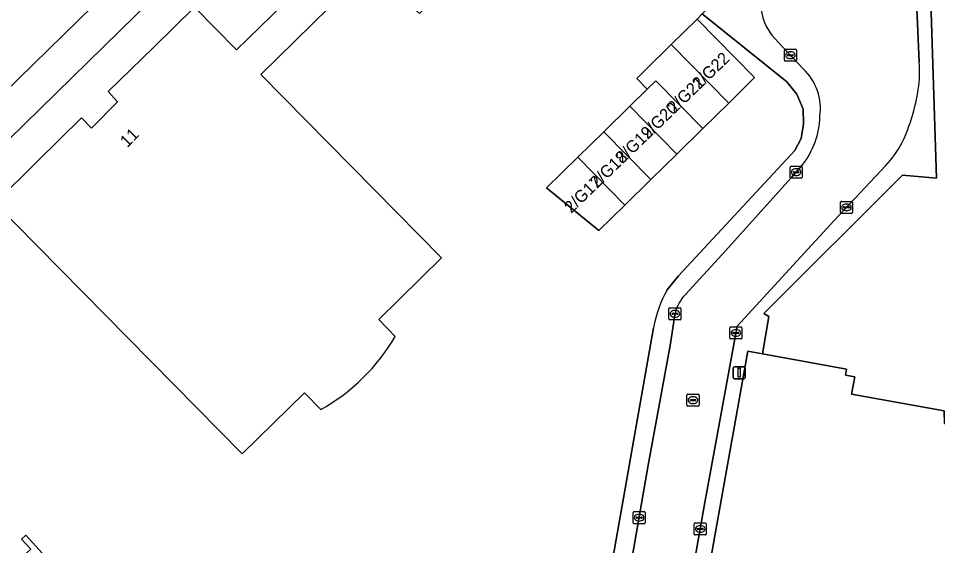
# Model space of a CAD drawing. Extents: x 161402 to 161933, y 381647 to 382315.
# Drawn here: x 161787.9 to 161864.2, y 382075.9 to 382119.7 of the extents above; entities that cross this region are included whole.
import ezdxf

# ---------------------------------------------------------------- set-up
doc = ezdxf.new("R2010")
doc.units = 0
for name, color, linetype in [('IMGEO_Erf', 7, 'Continuous'), ('IMGEO_Kolk', 7, 'Continuous'), ('IMGEO_Lichtmast', 7, 'Continuous'), ('IMGEO_Muur', 7, 'Continuous'), ('IMGEO_Pand', 7, 'Continuous'), ('IMGEO_Pand_nummerreeks', 7, 'Continuous'), ('IMGEO_Rijbaan_lokaal_gesloten', 7, 'Continuous'), ('IMGEO_Rijbaan_lokaal_open', 7, 'Continuous'), ('IMGEO_Rioolput', 7, 'Continuous'), ('IMGEO_Voetpad_gesloten', 7, 'Continuous'), ('IMGEO_Voetpad_open', 7, 'Continuous')]:
    doc.layers.add(name, color=color, linetype=linetype)

msp = doc.modelspace()

# ---------------------------------------------------------------- linework, layer by layer
at = {"layer": 'IMGEO_Erf'}
for points in [[(161864.813, 382185.757), (161863.347, 382184.324), (161863.181, 382184.507), (161862.906, 382184.222), (161863.062, 382184.049), (161858.604, 382179.691), (161858.378, 382179.885), (161858.103, 382179.58), (161858.236, 382179.449), (161857.746, 382179.014), (161845.138, 382166.658), (161826.48, 382148.395), (161804.249, 382126.529), (161781.67, 382104.382)], [(161812.975, 382087.217), (161811.601, 382088.614), (161806.434, 382083.531), (161789.417, 382100.81), (161785.909, 382104.373), (161789.402, 382107.818), (161793.08, 382111.447), (161793.922, 382110.604), (161796.076, 382112.783), (161795.307, 382113.643), (161799.066, 382117.315), (161802.484, 382120.653), (161805.97, 382117.113), (161810.796, 382121.845), (161807.594, 382125.104), (161806.847, 382124.385), (161806.553, 382124.686), (161817.329, 382135.274), (161851.932, 382169.271)], [(161841.719, 382097.173), (161842.653, 382098.334), (161852.306, 382108.752), (161852.848, 382109.73), (161853.024, 382110.948), (161853.013, 382112.179), (161852.482, 382113.414), (161851.638, 382114.461), (161844.618, 382120.095), (161853.957, 382129.629), (161859.667, 382135.458), (161869.551, 382145.549)], [(161826.819, 382125.706), (161821.145, 382120.119), (161820.85, 382120.418), (161821.62, 382121.174), (161817.967, 382124.889), (161807.983, 382115.074), (161822.985, 382099.813), (161817.767, 382094.694), (161819.142, 382093.297)], [(161836.652, 382071.701), (161840.585, 382094.002)], [(161783.505, 382056.018), (161783.263, 382058.701), (161776.645, 382071.618), (161786.037, 382076.43), (161787.222, 382074.116), (161788.878, 382075.604), (161788.117, 382076.444), (161788.484, 382076.777), (161796.387, 382068.043), (161796.339, 382068), (161797.532, 382065.679), (161799.064, 382066.435), (161805.902, 382053.086)]]:
    msp.add_lwpolyline(points, dxfattribs=at)
for points in [[(161885.051, 382130.105), (161872.557, 382142.66), (161863.229, 382133.182), (161864.069, 382106.453), (161861.265, 382106.705), (161849.74, 382095.198), (161850.155, 382094.961), (161849.637, 382091.837), (161856.605, 382090.577), (161856.514, 382090.075), (161857.282, 382089.936), (161857.022, 382088.5), (161864.705, 382087.108), (161864.747, 382086.071), (161881.604, 382083.709), (161886.502, 382086.978)], [(161831.708, 382105.633), (161834.296, 382108.178), (161836.452, 382110.297), (161838.608, 382112.417), (161840.063, 382113.848), (161839.185, 382114.74), (161839.886, 382115.429), (161842.042, 382117.548), (161844.198, 382119.667), (161848.979, 382114.803), (161846.823, 382112.684), (161844.667, 382110.565), (161842.512, 382108.446), (161840.356, 382106.326), (161838.2, 382104.207), (161836.044, 382102.088)]]:
    msp.add_lwpolyline(points, close=True, dxfattribs=at)
for centre, radius, start, end in [((161850.329, 382092.306), 9.89, 150.51987, 170.12441), ((161804.804, 382101.672), 16.604, 299.47668, 329.7093)]:
    msp.add_arc(centre, radius, start, end, dxfattribs=at)
at = {"layer": 'IMGEO_Kolk'}
for p, q in [((161851.446, 382116.238), (161851.446, 382117.09)), ((161851.521, 382117.164), (161852.373, 382117.164)), ((161851.934, 382116.944), (161851.959, 382116.944)), ((161852.447, 382117.09), (161852.447, 382116.238)), ((161852.373, 382116.164), (161851.521, 382116.164)), ((161851.705, 382116.658), (161851.705, 382116.67)), ((161852.143, 382116.621), (161851.745, 382116.621)), ((161851.748, 382116.707), (161852.146, 382116.707)), ((161851.957, 382116.384), (161851.932, 382116.384)), ((161852.189, 382116.67), (161852.189, 382116.658)), ((161851.921, 382106.512), (161851.921, 382107.364)), ((161851.996, 382107.438), (161852.848, 382107.438)), ((161852.18, 382106.932), (161852.18, 382106.944)), ((161852.223, 382106.981), (161852.621, 382106.981)), ((161852.409, 382107.218), (161852.434, 382107.218)), ((161852.664, 382106.944), (161852.664, 382106.932)), ((161852.922, 382107.364), (161852.922, 382106.512)), ((161852.848, 382106.438), (161851.996, 382106.438)), ((161852.618, 382106.895), (161852.22, 382106.895)), ((161852.432, 382106.658), (161852.407, 382106.658)), ((161856.101, 382103.59), (161856.101, 382104.442)), ((161856.176, 382104.516), (161857.028, 382104.516)), ((161856.36, 382104.01), (161856.36, 382104.022)), ((161856.798, 382103.973), (161856.4, 382103.973)), ((161856.403, 382104.059), (161856.801, 382104.059)), ((161856.589, 382104.296), (161856.614, 382104.296)), ((161856.844, 382104.022), (161856.844, 382104.01)), ((161857.102, 382104.442), (161857.102, 382103.59)), ((161857.028, 382103.516), (161856.176, 382103.516)), ((161856.612, 382103.736), (161856.587, 382103.736)), ((161841.861, 382094.749), (161841.861, 382095.601)), ((161841.936, 382095.675), (161842.788, 382095.675)), ((161842.862, 382095.601), (161842.862, 382094.749)), ((161842.12, 382095.169), (161842.12, 382095.181)), ((161842.558, 382095.132), (161842.16, 382095.132)), ((161842.163, 382095.218), (161842.561, 382095.218)), ((161842.372, 382094.895), (161842.347, 382094.895)), ((161842.349, 382095.455), (161842.374, 382095.455)), ((161842.604, 382095.181), (161842.604, 382095.169)), ((161842.788, 382094.675), (161841.936, 382094.675)), ((161846.92, 382093.157), (161846.92, 382094.009)), ((161846.995, 382094.083), (161847.847, 382094.083)), ((161847.921, 382094.009), (161847.921, 382093.157)), ((161847.179, 382093.577), (161847.179, 382093.589)), ((161847.617, 382093.54), (161847.219, 382093.54)), ((161847.222, 382093.626), (161847.62, 382093.626)), ((161847.431, 382093.303), (161847.406, 382093.303)), ((161847.408, 382093.863), (161847.433, 382093.863)), ((161847.663, 382093.589), (161847.663, 382093.577)), ((161847.847, 382093.083), (161846.995, 382093.083)), ((161838.964, 382078.733), (161839.816, 382078.733)), ((161838.889, 382077.807), (161838.889, 382078.659)), ((161839.148, 382078.227), (161839.148, 382078.239)), ((161839.586, 382078.19), (161839.188, 382078.19)), ((161839.191, 382078.276), (161839.589, 382078.276)), ((161839.4, 382077.953), (161839.375, 382077.953)), ((161839.377, 382078.513), (161839.402, 382078.513)), ((161839.632, 382078.239), (161839.632, 382078.227)), ((161839.89, 382078.659), (161839.89, 382077.807)), ((161839.816, 382077.733), (161838.964, 382077.733)), ((161843.958, 382076.869), (161843.958, 382077.721)), ((161844.033, 382077.795), (161844.885, 382077.795)), ((161844.217, 382077.289), (161844.217, 382077.301)), ((161844.655, 382077.252), (161844.257, 382077.252)), ((161844.26, 382077.338), (161844.658, 382077.338)), ((161844.446, 382077.575), (161844.471, 382077.575)), ((161844.701, 382077.301), (161844.701, 382077.289)), ((161844.959, 382077.721), (161844.959, 382076.869)), ((161844.885, 382076.795), (161844.033, 382076.795)), ((161844.469, 382077.015), (161844.444, 382077.015))]:
    msp.add_line(p, q, dxfattribs=at)
for points in [[(161851.446, 382116.238), (161851.446, 382117.09)], [(161851.521, 382117.164), (161852.373, 382117.164)], [(161852.447, 382117.09), (161852.447, 382116.238)], [(161852.373, 382116.164), (161851.521, 382116.164)], [(161851.921, 382106.512), (161851.921, 382107.364)], [(161851.996, 382107.438), (161852.848, 382107.438)], [(161852.922, 382107.364), (161852.922, 382106.512)], [(161852.848, 382106.438), (161851.996, 382106.438)], [(161856.101, 382103.59), (161856.101, 382104.442)], [(161856.176, 382104.516), (161857.028, 382104.516)], [(161857.102, 382104.442), (161857.102, 382103.59)], [(161857.028, 382103.516), (161856.176, 382103.516)], [(161841.861, 382094.749), (161841.861, 382095.601)], [(161841.936, 382095.675), (161842.788, 382095.675)], [(161842.862, 382095.601), (161842.862, 382094.749)], [(161842.788, 382094.675), (161841.936, 382094.675)], [(161846.92, 382093.157), (161846.92, 382094.009)], [(161846.995, 382094.083), (161847.847, 382094.083)], [(161847.921, 382094.009), (161847.921, 382093.157)], [(161847.847, 382093.083), (161846.995, 382093.083)], [(161838.964, 382078.733), (161839.816, 382078.733)], [(161838.889, 382077.807), (161838.889, 382078.659)], [(161839.89, 382078.659), (161839.89, 382077.807)], [(161839.816, 382077.733), (161838.964, 382077.733)], [(161843.958, 382076.869), (161843.958, 382077.721)], [(161844.033, 382077.795), (161844.885, 382077.795)], [(161844.959, 382077.721), (161844.959, 382076.869)], [(161844.885, 382076.795), (161844.033, 382076.795)]]:
    msp.add_lwpolyline(points, dxfattribs=at)
for centre, radius, start, end in [((161851.523, 382117.088), 0.0765, 91.55205, 178.44795), ((161851.523, 382117.088), 0.0765, 91.55205, 178.44795), ((161852.371, 382117.088), 0.0765, 1.55205, 88.44795), ((161852.371, 382117.088), 0.0765, 1.55205, 88.44795), ((161851.523, 382116.24), 0.0765, 181.55205, 268.44795), ((161851.523, 382116.24), 0.0765, 181.55205, 268.44795), ((161851.745, 382116.667), 0.0403, 85.87752, 175.75265), ((161851.742, 382116.657), 0.0366, 178.93798, 274.71019), ((161852.146, 382116.664), 0.043, 264.86636, 352.45326), ((161852.15, 382116.669), 0.0386, 1.73085, 96.63898), ((161852.371, 382116.24), 0.0765, 271.55205, 358.44795), ((161852.371, 382116.24), 0.0765, 271.55205, 358.44795), ((161851.998, 382107.362), 0.0765, 91.55205, 178.44795), ((161851.998, 382107.362), 0.0765, 91.55205, 178.44795), ((161852.22, 382106.941), 0.0403, 85.87752, 175.75265), ((161852.217, 382106.931), 0.0366, 178.93798, 274.71019), ((161852.621, 382106.938), 0.043, 264.86636, 352.45326), ((161852.625, 382106.943), 0.0386, 1.73085, 96.63898), ((161852.846, 382107.362), 0.0765, 1.55205, 88.44795), ((161852.846, 382107.362), 0.0765, 1.55205, 88.44795), ((161851.998, 382106.514), 0.0765, 181.55205, 268.44795), ((161851.998, 382106.514), 0.0765, 181.55205, 268.44795), ((161852.846, 382106.514), 0.0765, 271.55205, 358.44795), ((161852.846, 382106.514), 0.0765, 271.55205, 358.44795), ((161856.178, 382104.44), 0.0765, 91.55205, 178.44795), ((161856.178, 382104.44), 0.0765, 91.55205, 178.44795), ((161856.4, 382104.019), 0.0403, 85.87752, 175.75265), ((161856.397, 382104.009), 0.0366, 178.93798, 274.71019), ((161856.801, 382104.016), 0.043, 264.86636, 352.45326), ((161856.805, 382104.021), 0.0386, 1.73085, 96.63898), ((161857.026, 382104.44), 0.0765, 1.55205, 88.44795), ((161857.026, 382104.44), 0.0765, 1.55205, 88.44795), ((161856.178, 382103.592), 0.0765, 181.55205, 268.44795), ((161856.178, 382103.592), 0.0765, 181.55205, 268.44795), ((161857.026, 382103.592), 0.0765, 271.55205, 358.44795), ((161857.026, 382103.592), 0.0765, 271.55205, 358.44795), ((161841.938, 382095.599), 0.0765, 91.55205, 178.44795), ((161841.938, 382095.599), 0.0765, 91.55205, 178.44795), ((161842.786, 382095.599), 0.0765, 1.55205, 88.44795), ((161842.786, 382095.599), 0.0765, 1.55205, 88.44795), ((161841.938, 382094.751), 0.0765, 181.55205, 268.44795), ((161841.938, 382094.751), 0.0765, 181.55205, 268.44795), ((161842.16, 382095.178), 0.0403, 85.87752, 175.75265), ((161842.157, 382095.168), 0.0366, 178.93798, 274.71019), ((161842.561, 382095.175), 0.043, 264.86636, 352.45326), ((161842.565, 382095.18), 0.0386, 1.73085, 96.63898), ((161842.786, 382094.751), 0.0765, 271.55205, 358.44795), ((161842.786, 382094.751), 0.0765, 271.55205, 358.44795), ((161846.997, 382094.007), 0.0765, 91.55205, 178.44795), ((161846.997, 382094.007), 0.0765, 91.55205, 178.44795), ((161847.845, 382094.007), 0.0765, 1.55205, 88.44795), ((161847.845, 382094.007), 0.0765, 1.55205, 88.44795), ((161847.219, 382093.586), 0.0403, 85.87752, 175.75265), ((161847.216, 382093.576), 0.0366, 178.93798, 274.71019), ((161847.62, 382093.583), 0.043, 264.86636, 352.45326), ((161847.624, 382093.588), 0.0386, 1.73085, 96.63898), ((161846.997, 382093.159), 0.0765, 181.55205, 268.44795), ((161846.997, 382093.159), 0.0765, 181.55205, 268.44795), ((161847.845, 382093.159), 0.0765, 271.55205, 358.44795), ((161847.845, 382093.159), 0.0765, 271.55205, 358.44795), ((161838.966, 382078.657), 0.0765, 91.55205, 178.44795), ((161838.966, 382078.657), 0.0765, 91.55205, 178.44795), ((161839.814, 382078.657), 0.0765, 1.55205, 88.44795), ((161839.814, 382078.657), 0.0765, 1.55205, 88.44795), ((161839.188, 382078.236), 0.0403, 85.87752, 175.75265), ((161839.185, 382078.226), 0.0366, 178.93798, 274.71019), ((161839.589, 382078.233), 0.043, 264.86636, 352.45326), ((161839.593, 382078.238), 0.0386, 1.73085, 96.63898), ((161838.966, 382077.809), 0.0765, 181.55205, 268.44795), ((161838.966, 382077.809), 0.0765, 181.55205, 268.44795), ((161839.814, 382077.809), 0.0765, 271.55205, 358.44795), ((161839.814, 382077.809), 0.0765, 271.55205, 358.44795), ((161844.035, 382077.719), 0.0765, 91.55205, 178.44795), ((161844.035, 382077.719), 0.0765, 91.55205, 178.44795), ((161844.257, 382077.298), 0.0403, 85.87752, 175.75265), ((161844.254, 382077.288), 0.0366, 178.93798, 274.71019), ((161844.658, 382077.295), 0.043, 264.86636, 352.45326), ((161844.662, 382077.3), 0.0386, 1.73085, 96.63898), ((161844.883, 382077.719), 0.0765, 1.55205, 88.44795), ((161844.883, 382077.719), 0.0765, 1.55205, 88.44795), ((161844.035, 382076.871), 0.0765, 181.55205, 268.44795), ((161844.035, 382076.871), 0.0765, 181.55205, 268.44795), ((161844.883, 382076.871), 0.0765, 271.55205, 358.44795), ((161844.883, 382076.871), 0.0765, 271.55205, 358.44795)]:
    msp.add_arc(centre, radius, start, end, dxfattribs=at)
for centre, major_axis, ratio, start_param, end_param in [((161851.933, 382116.664), (-0.387, 0.002), 0.722429, 4.712389, 7.853982), ((161851.958, 382116.664), (-0.39, 0.002), 0.717154, 1.570796, 4.712389), ((161852.408, 382106.938), (-0.387, 0.002), 0.722429, 4.712389, 7.853982), ((161852.433, 382106.938), (-0.39, 0.002), 0.717154, 1.570796, 4.712389), ((161856.588, 382104.016), (-0.387, 0.002), 0.722429, 4.712389, 7.853982), ((161856.613, 382104.016), (-0.39, 0.002), 0.717154, 1.570796, 4.712389), ((161842.348, 382095.175), (-0.387, 0.002), 0.722429, 4.712389, 7.853982), ((161842.373, 382095.175), (-0.39, 0.002), 0.717154, 1.570796, 4.712389), ((161847.407, 382093.583), (-0.387, 0.002), 0.722429, 4.712389, 7.853982), ((161847.432, 382093.583), (-0.39, 0.002), 0.717154, 1.570796, 4.712389), ((161839.376, 382078.233), (-0.387, 0.002), 0.722429, 4.712389, 7.853982), ((161839.401, 382078.233), (-0.39, 0.002), 0.717154, 1.570796, 4.712389), ((161844.445, 382077.295), (-0.387, 0.002), 0.722429, 4.712389, 7.853982), ((161844.47, 382077.295), (-0.39, 0.002), 0.717154, 1.570796, 4.712389)]:
    msp.add_ellipse(centre, major_axis=major_axis, ratio=ratio, start_param=start_param, end_param=end_param, dxfattribs=at)
at = {"layer": 'IMGEO_Lichtmast'}
for p, q in [((161847.199, 382089.88), (161847.199, 382090.68)), ((161847.199, 382090.68), (161847.199, 382089.88)), ((161847.299, 382090.78), (161848.089, 382090.78)), ((161848.089, 382090.78), (161847.299, 382090.78)), ((161848.189, 382090.68), (161848.189, 382089.88)), ((161848.189, 382089.88), (161848.189, 382090.68)), ((161848.089, 382089.78), (161847.299, 382089.78)), ((161847.299, 382089.78), (161848.089, 382089.78))]:
    msp.add_line(p, q, dxfattribs=at)
msp.add_lwpolyline([(161847.619, 382090.655), (161847.769, 382090.655), (161847.769, 382089.905), (161847.619, 382089.905), (161847.619, 382090.655)], dxfattribs=at)
for centre, start, end in [((161847.299, 382090.68), 90, 180), ((161847.299, 382090.68), 90, 180), ((161848.089, 382090.68), 0, 90), ((161848.089, 382090.68), 360, 90), ((161847.299, 382089.88), 180, 270), ((161847.299, 382089.88), 180, 270), ((161848.089, 382089.88), 270, 0), ((161848.089, 382089.88), 270, 0)]:
    msp.add_arc(centre, 0.1, start, end, dxfattribs=at)
at = {"layer": 'IMGEO_Muur'}
msp.add_lwpolyline([(161844.618, 382120.095), (161844.198, 382119.667)], dxfattribs=at)
at = {"layer": 'IMGEO_Pand'}
for points in [[(161819.142, 382093.297), (161817.767, 382094.694), (161822.985, 382099.813), (161807.983, 382115.074), (161817.967, 382124.889)], [(161810.796, 382121.845), (161805.97, 382117.113), (161802.484, 382120.653), (161799.066, 382117.315), (161795.307, 382113.643), (161796.076, 382112.783), (161793.922, 382110.604), (161793.08, 382111.447), (161789.402, 382107.818), (161785.909, 382104.373), (161789.417, 382100.81), (161806.434, 382083.531), (161811.601, 382088.614), (161812.975, 382087.217)], [(161796.339, 382068), (161796.387, 382068.043), (161788.484, 382076.777), (161788.117, 382076.444), (161788.878, 382075.604), (161787.222, 382074.116), (161786.037, 382076.43), (161776.645, 382071.618), (161783.263, 382058.701), (161783.505, 382056.018)]]:
    msp.add_lwpolyline(points, dxfattribs=at)
for points in [[(161846.823, 382112.684), (161848.979, 382114.803), (161844.198, 382119.667), (161842.042, 382117.548)], [(161842.042, 382117.548), (161839.886, 382115.429), (161839.185, 382114.74), (161840.063, 382113.848), (161840.763, 382114.537), (161844.667, 382110.565), (161846.823, 382112.684)], [(161840.063, 382113.848), (161838.608, 382112.417), (161842.512, 382108.446), (161844.667, 382110.565), (161840.763, 382114.537)], [(161838.608, 382112.417), (161836.452, 382110.297), (161840.356, 382106.326), (161842.512, 382108.446)], [(161836.452, 382110.297), (161834.296, 382108.178), (161838.2, 382104.207), (161840.356, 382106.326)], [(161834.296, 382108.178), (161831.708, 382105.633), (161836.044, 382102.088), (161838.2, 382104.207)], [(161881.604, 382083.709), (161864.747, 382086.071), (161864.705, 382087.108), (161857.022, 382088.5), (161857.282, 382089.936), (161856.514, 382090.075), (161856.605, 382090.577), (161849.637, 382091.837), (161848.409, 382092.059), (161845.824, 382077.508), (161842.463, 382058.722), (161841.73, 382054.571), (161852.314, 382052.645), (161867.831, 382049.852), (161874.803, 382048.597), (161875.966, 382054.535), (161876.056, 382054.517), (161876.327, 382055.897), (161879.777, 382073.754), (161879.674, 382073.772), (161879.866, 382074.825), (161879.984, 382074.802), (161880.941, 382079.709), (161880.846, 382079.728)]]:
    msp.add_lwpolyline(points, close=True, dxfattribs=at)
msp.add_arc((161804.804, 382101.672), 16.604, 299.47668, 329.7093, dxfattribs=at)
at = {"layer": 'IMGEO_Rijbaan_lokaal_gesloten'}
msp.add_lwpolyline([(161775.438, 382102.569), (161800.253, 382126.852)], dxfattribs=at)
at = {"layer": 'IMGEO_Rijbaan_lokaal_open'}
for points in [[(161840.202, 382046.042), (161841.73, 382054.571), (161842.463, 382058.722), (161845.824, 382077.508), (161848.409, 382092.059), (161849.637, 382091.837), (161850.155, 382094.961), (161849.74, 382095.198), (161861.265, 382106.705), (161864.069, 382106.453), (161863.229, 382133.182), (161861.825, 382133.473), (161862.193, 382125.995), (161862.49, 382119.308), (161862.638, 382116.087)], [(161862.638, 382116.087), (161862.49, 382119.308), (161862.193, 382125.995), (161861.825, 382133.473)], [(161850.964, 382117.721), (161853.009, 382115.528)], [(161859.869, 382107.508), (161855.583, 382102.928), (161847.522, 382094.137), (161844.797, 382079.199), (161841.729, 382061.924), (161839.275, 382047.946), (161836.784, 382033.46), (161833.899, 382016.966), (161830.695, 382000), (161827.554, 381983.498), (161825.196, 381970.616), (161825.164, 381970.44), (161822.54, 381956.991), (161822.45, 381956.505), (161823.681, 381955.575), (161824.173, 381957.682), (161825.719, 381965.932), (161826.684, 381971.203), (161827.883, 381977.756), (161828.609, 381981.506), (161828.968, 381983.243), (161830.987, 381994.574), (161831.954, 382000), (161840.202, 382046.042)], [(161839.275, 382047.946), (161841.729, 382061.924), (161844.797, 382079.199), (161847.522, 382094.137), (161855.583, 382102.928), (161859.869, 382107.508)], [(161852.954, 382107.561), (161851.992, 382106.433), (161846.565, 382100.416), (161843.23, 382096.775)], [(161842.377, 382095.257), (161841.953, 382092.549), (161840.146, 382082.597), (161838.823, 382074.942)]]:
    msp.add_lwpolyline(points, dxfattribs=at)
for centre, radius, start, end in [((161854.099, 382121.144), 4.641, 147.48062, 227.51711), ((161852.834, 382115.281), 9.837, 351.6182, 4.69977), ((161852.834, 382115.281), 9.837, 351.6182, 4.69977), ((161849.885, 382112.205), 4.56, 351.95565, 46.77), ((161846.52, 382116.258), 16.226, 335.05094, 351.45336), ((161846.52, 382116.258), 16.226, 335.05094, 351.45336), ((161847.556, 382111.775), 6.848, 322.02122, 358.25851), ((161853.409, 382113.568), 8.857, 316.83009, 332.03202), ((161853.409, 382113.568), 8.857, 316.83009, 332.03202), ((161845.648, 382094.418), 3.376, 135.72469, 165.60999)]:
    msp.add_arc(centre, radius, start, end, dxfattribs=at)
at = {"layer": 'IMGEO_Rioolput'}
for p, q in [((161843.358, 382087.572), (161843.358, 382088.424)), ((161843.433, 382088.498), (161844.285, 382088.498)), ((161843.617, 382087.992), (161843.617, 382088.004)), ((161844.055, 382087.955), (161843.657, 382087.955)), ((161843.66, 382088.041), (161844.058, 382088.041)), ((161843.846, 382088.278), (161843.871, 382088.278)), ((161844.101, 382088.004), (161844.101, 382087.992)), ((161844.359, 382088.424), (161844.359, 382087.572)), ((161844.285, 382087.498), (161843.433, 382087.498)), ((161843.869, 382087.718), (161843.844, 382087.718))]:
    msp.add_line(p, q, dxfattribs=at)
for points in [[(161843.358, 382087.572), (161843.358, 382088.424)], [(161843.433, 382088.498), (161844.285, 382088.498)], [(161844.359, 382088.424), (161844.359, 382087.572)], [(161844.285, 382087.498), (161843.433, 382087.498)]]:
    msp.add_lwpolyline(points, dxfattribs=at)
for centre, radius, start, end in [((161843.435, 382088.422), 0.0765, 91.55205, 178.44795), ((161843.435, 382088.422), 0.0765, 91.55205, 178.44795), ((161843.657, 382088.001), 0.0403, 85.87752, 175.75265), ((161843.654, 382087.991), 0.0366, 178.93798, 274.71019), ((161844.058, 382087.998), 0.043, 264.86636, 352.45326), ((161844.062, 382088.003), 0.0386, 1.73085, 96.63898), ((161844.283, 382088.422), 0.0765, 1.55205, 88.44795), ((161844.283, 382088.422), 0.0765, 1.55205, 88.44795), ((161843.435, 382087.574), 0.0765, 181.55205, 268.44795), ((161843.435, 382087.574), 0.0765, 181.55205, 268.44795), ((161844.283, 382087.574), 0.0765, 271.55205, 358.44795), ((161844.283, 382087.574), 0.0765, 271.55205, 358.44795)]:
    msp.add_arc(centre, radius, start, end, dxfattribs=at)
for centre, major_axis, ratio, start_param, end_param in [((161843.845, 382087.998), (-0.387, 0.002), 0.722429, 4.712389, 7.853982), ((161843.87, 382087.998), (-0.39, 0.002), 0.717154, 1.570796, 4.712389)]:
    msp.add_ellipse(centre, major_axis=major_axis, ratio=ratio, start_param=start_param, end_param=end_param, dxfattribs=at)
at = {"layer": 'IMGEO_Voetpad_gesloten'}
for points in [[(161850.185, 382123.639), (161853.771, 382127.471), (161854.901, 382128.683), (161860.18, 382134.346), (161859.667, 382135.458), (161853.957, 382129.629), (161844.618, 382120.095), (161851.638, 382114.461), (161852.482, 382113.414), (161853.013, 382112.179), (161853.024, 382110.948), (161852.848, 382109.73), (161852.306, 382108.752), (161842.653, 382098.334), (161841.719, 382097.173)], [(161853.009, 382115.528), (161850.964, 382117.721)], [(161843.23, 382096.775), (161846.565, 382100.416), (161851.992, 382106.433), (161852.954, 382107.561)], [(161840.146, 382082.597), (161841.953, 382092.549), (161842.377, 382095.257)], [(161840.585, 382094.002), (161836.652, 382071.701), (161838.217, 382071.422), (161838.823, 382074.942), (161840.146, 382082.597)]]:
    msp.add_lwpolyline(points, dxfattribs=at)
for centre, radius, start, end in [((161854.099, 382121.144), 4.641, 147.48062, 227.51711), ((161849.885, 382112.205), 4.56, 351.95565, 46.77), ((161847.556, 382111.775), 6.848, 322.02122, 358.25851), ((161850.329, 382092.306), 9.89, 150.51987, 170.12441), ((161845.648, 382094.418), 3.376, 135.72469, 165.60999)]:
    msp.add_arc(centre, radius, start, end, dxfattribs=at)
at = {"layer": 'IMGEO_Voetpad_open'}
for points in [[(161761.87, 381990.395), (161762.821, 381997.456), (161773.703, 382076.916), (161776.756, 382099.569), (161777.238, 382100.058), (161781.67, 382104.382), (161804.249, 382126.529), (161826.48, 382148.395), (161845.138, 382166.658), (161857.746, 382179.014)], [(161807.598, 382135.507), (161808.326, 382134.752), (161805.139, 382131.633), (161802.994, 382129.534), (161803.304, 382129.202), (161800.583, 382126.535), (161800.253, 382126.852), (161775.438, 382102.569)]]:
    msp.add_lwpolyline(points, dxfattribs=at)

# ---------------------------------------------------------------- texts
at = {"layer": 'IMGEO_Pand_nummerreeks'}
for s, rotation, p in [('2/G22', 44.08335, (161844.369, 382113.758)), ('2/G21', 44.08337, (161842.315, 382111.769)), ('2/G20', 44.08337, (161840.1, 382109.624)), ('11', 45.33058, (161796.895, 382108.946)), ('2/G19', 44.08337, (161838.023, 382107.612)), ('2/G18', 44.08337, (161835.89, 382105.546)), ('2/G17', 44.08337, (161833.75, 382103.473))]:
    msp.add_text(s, height=1, rotation=rotation, dxfattribs=at).set_placement(p)

doc.saveas('drawing.dxf')
